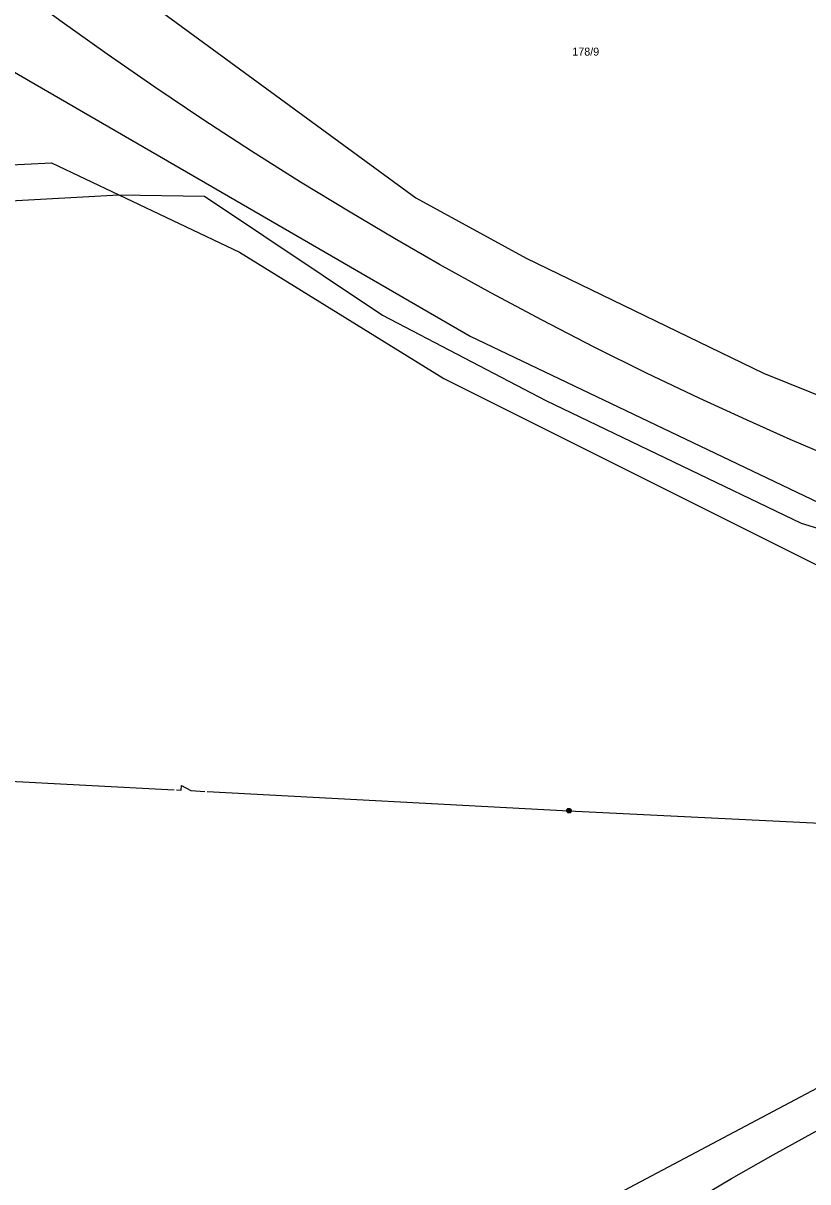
# Model space of a CAD drawing. Extents: x -757994 to -755874, y -1047691 to -1046119.
# Drawn here: x -756667.9 to -756584.6, y -1046585.4 to -1046462.4 of the extents above; entities that cross this region are included whole.
import ezdxf

# ---------------------------------------------------------------- set-up
doc = ezdxf.new("R2010")
doc.units = 0
doc.layers.add('katastrální mapa', color=7, linetype='Continuous')

msp = doc.modelspace()

# ---------------------------------------------------------------- linework, layer by layer
at = {"layer": 'katastrální mapa'}
for p, q in [((-756654.03, -1046460.61), (-756626.19, -1046480.96)), ((-756669.72, -1046467.08), (-756620.45, -1046495.62)), ((-756694.28, -1046478.65), (-756664.9, -1046477.23)), ((-756664.9, -1046477.23), (-756657.74, -1046480.63)), ((-756669.89, -1046481.3), (-756657.74, -1046480.63)), ((-756657.74, -1046480.63), (-756648.66, -1046480.76)), ((-756657.74, -1046480.63), (-756644.94, -1046486.72)), ((-756648.66, -1046480.76), (-756629.76, -1046493.4)), ((-756626.19, -1046480.96), (-756614.48, -1046487.34)), ((-756644.94, -1046486.72), (-756623.22, -1046500.13)), ((-756614.48, -1046487.34), (-756589.28, -1046499.56)), ((-756629.76, -1046493.4), (-756612.39, -1046502.47)), ((-756620.45, -1046495.62), (-756573.48, -1046518.08)), ((-756623.22, -1046500.13), (-756579.1, -1046522.22)), ((-756589.28, -1046499.56), (-756568.09, -1046508.17)), ((-756612.39, -1046502.47), (-756585.29, -1046515.5)), ((-756585.29, -1046515.5), (-756579.45, -1046517.3)), ((-756690.27, -1046541.76), (-756651.86, -1046543.8)), ((-756648.36, -1046543.98), (-756609.95, -1046546.02)), ((-756609.95, -1046546.02), (-756571.52, -1046547.95)), ((-756608.85, -1046588.84), (-756559.96, -1046562.95))]:
    msp.add_line(p, q, dxfattribs=at)
for points in [[(-756591.11, -1046504.53), (-756596.12, -1046502.22), (-756601.72, -1046499.55), (-756607.27, -1046496.79), (-756612.78, -1046493.95), (-756618.25, -1046491.02), (-756623.68, -1046488.02), (-756628.46, -1046485.27), (-756633.19, -1046482.48), (-756638.45, -1046479.28), (-756643.66, -1046476), (-756648.82, -1046472.64), (-756653.93, -1046469.21), (-756658.99, -1046465.7), (-756663.99, -1046462.12), (-756668.41, -1046458.86)], [(-756524.73, -1046528), (-756530.24, -1046526.52), (-756536.56, -1046524.72), (-756542.84, -1046522.83), (-756549.09, -1046520.84), (-756555.31, -1046518.74), (-756561.5, -1046516.56), (-756566.85, -1046514.57), (-756571.61, -1046512.74), (-756576.58, -1046510.76), (-756581.53, -1046508.71), (-756586.45, -1046506.6), (-756591.11, -1046504.53)], [(-756651.61, -1046543.81), (-756651.11, -1046543.84), (-756651.08, -1046543.34), (-756650.11, -1046543.89), (-756648.61, -1046543.97)], [(-756610.02, -1046545.78), (-756609.87, -1046545.78), (-756609.74, -1046545.87), (-756609.7, -1046546.02), (-756609.74, -1046546.16), (-756609.87, -1046546.25), (-756610.02, -1046546.25), (-756610.15, -1046546.16), (-756610.2, -1046546.02), (-756610.15, -1046545.87), (-756610.02, -1046545.78), (-756610.01, -1046545.8), (-756609.89, -1046545.8), (-756609.81, -1046545.84), (-756610.09, -1046545.84), (-756610.13, -1046545.88), (-756609.77, -1046545.88), (-756609.77, -1046545.92), (-756610.13, -1046545.92), (-756610.15, -1046545.96), (-756609.75, -1046545.96), (-756609.73, -1046546), (-756610.17, -1046546), (-756610.17, -1046546.04), (-756609.73, -1046546.04), (-756609.74, -1046546.08), (-756610.15, -1046546.08), (-756610.15, -1046546.12), (-756609.74, -1046546.12), (-756609.76, -1046546.16), (-756610.12, -1046546.16), (-756610.09, -1046546.2), (-756609.8, -1046546.2), (-756609.86, -1046546.24), (-756610.03, -1046546.24)], [(-756627.26, -1046608.56), (-756623.41, -1046605.58), (-756618.91, -1046602.24), (-756614.35, -1046598.97), (-756609.74, -1046595.8), (-756605.06, -1046592.7), (-756600.95, -1046590.09), (-756597.03, -1046587.67), (-756592.68, -1046585.08), (-756588.28, -1046582.57), (-756583.84, -1046580.12), (-756579.36, -1046577.75), (-756575.25, -1046575.67)]]:
    msp.add_lwpolyline(points, dxfattribs=at)

# ---------------------------------------------------------------- texts
msp.add_text('178/9', height=0.85, dxfattribs=at).set_placement((-756609.59, -1046465.85))

doc.saveas('drawing.dxf')
